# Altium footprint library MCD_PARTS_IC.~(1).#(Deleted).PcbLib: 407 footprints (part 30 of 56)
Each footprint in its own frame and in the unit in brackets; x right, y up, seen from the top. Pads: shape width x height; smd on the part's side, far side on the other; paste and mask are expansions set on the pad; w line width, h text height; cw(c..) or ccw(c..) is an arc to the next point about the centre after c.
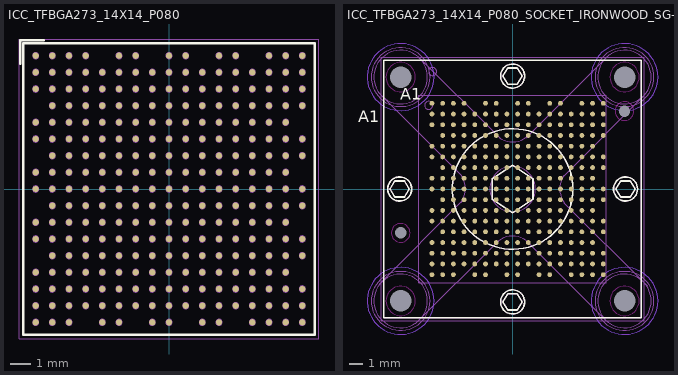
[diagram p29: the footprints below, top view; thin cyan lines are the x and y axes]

## ICC_TFBGA273_14X14_P080 [mm] "MCD-03616"
height 1.2
pads (273):
  round 0.3 smd mask+0.05: A1(-6.4,6.4) A2(-5.6,6.4) A3(-4.8,6.4) A4(-4,6.4) A6(-2.4,6.4) A7(-1.6,6.4) A9(0,6.4) A10(0.8,6.4) A12(2.4,6.4) A13(3.2,6.4) A15(4.8,6.4) A16(5.6,6.4) A17(6.4,6.4) B1(-6.4,5.6) B2(-5.6,5.6) B3(-4.8,5.6) B4(-4,5.6) B5(-3.2,5.6) B6(-2.4,5.6) B7(-1.6,5.6) B8(-0.8,5.6) B9(0,5.6) B10(0.8,5.6) B11(1.6,5.6) B12(2.4,5.6) B13(3.2,5.6) B14(4,5.6) B15(4.8,5.6) B16(5.6,5.6) B17(6.4,5.6) C1(-6.4,4.8) C2(-5.6,4.8) C3(-4.8,4.8) C4(-4,4.8) C5(-3.2,4.8) C6(-2.4,4.8) C7(-1.6,4.8) C8(-0.8,4.8) C9(0,4.8) C10(0.8,4.8) C11(1.6,4.8) C12(2.4,4.8) C13(3.2,4.8) C14(4,4.8) C15(4.8,4.8) C16(5.6,4.8) C17(6.4,4.8) D2(-5.6,4) D3(-4.8,4) D4(-4,4) D5(-3.2,4) D6(-2.4,4) D7(-1.6,4) D8(-0.8,4) D9(0,4) D10(0.8,4) D11(1.6,4) D12(2.4,4) D13(3.2,4) D14(4,4) D15(4.8,4) D16(5.6,4) D17(6.4,4) E1(-6.4,3.2) E2(-5.6,3.2) E3(-4.8,3.2) E4(-4,3.2) E5(-3.2,3.2) E6(-2.4,3.2) E7(-1.6,3.2) E8(-0.8,3.2) E9(0,3.2) E10(0.8,3.2) E11(1.6,3.2) E12(2.4,3.2) E13(3.2,3.2) E14(4,3.2) E15(4.8,3.2) E16(5.6,3.2) F1(-6.4,2.4) F2(-5.6,2.4) F3(-4.8,2.4) F4(-4,2.4) F5(-3.2,2.4) F6(-2.4,2.4) F7(-1.6,2.4) F8(-0.8,2.4) F9(0,2.4) F10(0.8,2.4) F11(1.6,2.4) F12(2.4,2.4) F13(3.2,2.4) F14(4,2.4) F15(4.8,2.4) F16(5.6,2.4) F17(6.4,2.4) G2(-5.6,1.6) G3(-4.8,1.6) G4(-4,1.6) G5(-3.2,1.6) G6(-2.4,1.6) G7(-1.6,1.6) G8(-0.8,1.6) G9(0,1.6) G10(0.8,1.6) G11(1.6,1.6) G12(2.4,1.6) G13(3.2,1.6) G14(4,1.6) G15(4.8,1.6) G16(5.6,1.6) G17(6.4,1.6) H1(-6.4,0.8) H2(-5.6,0.8) H3(-4.8,0.8) H4(-4,0.8) H5(-3.2,0.8) H6(-2.4,0.8) H7(-1.6,0.8) H8(-0.8,0.8) H9(0,0.8) H10(0.8,0.8) H11(1.6,0.8) H12(2.4,0.8) H13(3.2,0.8) H14(4,0.8) H15(4.8,0.8) H16(5.6,0.8) J1(-6.4,0) J2(-5.6,0) J3(-4.8,0) J4(-4,0) J5(-3.2,0) J6(-2.4,0) J7(-1.6,0) J8(-0.8,0) J9(0,0) J10(0.8,0) J11(1.6,0) J12(2.4,0) J13(3.2,0) J14(4,0) J15(4.8,0) J16(5.6,0) J17(6.4,0) K2(-5.6,-0.8) K3(-4.8,-0.8) K4(-4,-0.8) K5(-3.2,-0.8) K6(-2.4,-0.8) K7(-1.6,-0.8) K8(-0.8,-0.8) K9(0,-0.8) K10(0.8,-0.8) K11(1.6,-0.8) K12(2.4,-0.8) K13(3.2,-0.8) K14(4,-0.8) K15(4.8,-0.8) K16(5.6,-0.8) K17(6.4,-0.8) L1(-6.4,-1.6) L2(-5.6,-1.6) L3(-4.8,-1.6) L4(-4,-1.6) L5(-3.2,-1.6) L6(-2.4,-1.6) L7(-1.6,-1.6) L8(-0.8,-1.6) L9(0,-1.6) L10(0.8,-1.6) L11(1.6,-1.6) L12(2.4,-1.6) L13(3.2,-1.6) L14(4,-1.6) L15(4.8,-1.6) L16(5.6,-1.6) M1(-6.4,-2.4) M2(-5.6,-2.4) M3(-4.8,-2.4) M4(-4,-2.4) M5(-3.2,-2.4) M6(-2.4,-2.4) M7(-1.6,-2.4) M8(-0.8,-2.4) M9(0,-2.4) M10(0.8,-2.4) M11(1.6,-2.4) M12(2.4,-2.4) M13(3.2,-2.4) M14(4,-2.4) M15(4.8,-2.4) M16(5.6,-2.4) M17(6.4,-2.4) N2(-5.6,-3.2) N3(-4.8,-3.2) N4(-4,-3.2) N5(-3.2,-3.2) N6(-2.4,-3.2) N7(-1.6,-3.2) N8(-0.8,-3.2) N9(0,-3.2) N10(0.8,-3.2) N11(1.6,-3.2) N12(2.4,-3.2) N13(3.2,-3.2) N14(4,-3.2) N15(4.8,-3.2) N16(5.6,-3.2) N17(6.4,-3.2) P1(-6.4,-4) P2(-5.6,-4) P3(-4.8,-4) P4(-4,-4) P5(-3.2,-4) P6(-2.4,-4) P7(-1.6,-4) P8(-0.8,-4) P9(0,-4) P10(0.8,-4) P11(1.6,-4) P12(2.4,-4) P13(3.2,-4) P14(4,-4) P15(4.8,-4) P16(5.6,-4) R1(-6.4,-4.8) R2(-5.6,-4.8) R3(-4.8,-4.8) R4(-4,-4.8) R5(-3.2,-4.8) R6(-2.4,-4.8) R7(-1.6,-4.8) R8(-0.8,-4.8) R9(0,-4.8) R10(0.8,-4.8) R11(1.6,-4.8) R12(2.4,-4.8) R13(3.2,-4.8) R14(4,-4.8) R15(4.8,-4.8) R16(5.6,-4.8) R17(6.4,-4.8) T1(-6.4,-5.6) T2(-5.6,-5.6) T3(-4.8,-5.6) T4(-4,-5.6) T5(-3.2,-5.6) T6(-2.4,-5.6) T7(-1.6,-5.6) T8(-0.8,-5.6) T9(0,-5.6) T10(0.8,-5.6) T11(1.6,-5.6) T12(2.4,-5.6) T13(3.2,-5.6) T14(4,-5.6) T15(4.8,-5.6) T16(5.6,-5.6) T17(6.4,-5.6) U1(-6.4,-6.4) U2(-5.6,-6.4) U3(-4.8,-6.4) U5(-3.2,-6.4) U6(-2.4,-6.4) U8(-0.8,-6.4) U9(0,-6.4) U11(1.6,-6.4) U12(2.4,-6.4) U14(4,-6.4) U15(4.8,-6.4) U16(5.6,-6.4) U17(6.4,-6.4)
Top Overlay:
  lines w0.12: -7.15,6 -7.15,7.15 -6,7.15 ; -7,-7 -7,7 7,7 7,-7 -7,-7
M14-Top Assembly:
  drawing of 277 lines, arcs and shapes, not listed
  text "A1" at -6.865,6.079 h1
  text "'.Designator'" at 0,0 h0.75
M16-Top Courtyard:
  lines w0.01: -7.2,-7.2 7.2,-7.2 7.2,7.2 -7.2,7.2 -7.2,-7.2
3D body: height 1.2, standoff 0.29, extent -7,-7 7,7
3D body: height 1.21, standoff 1.2, extent -6.675,5.85 -5.875,6.65
3D body: height 0.37, standoff -0.03, extent -6.6,6.2 -6.2,6.6
3D body: height 0.37, standoff -0.03, extent -5.8,6.2 -5.4,6.6
3D body: height 0.37, standoff -0.03, extent -5,6.2 -4.6,6.6
3D body: height 0.37, standoff -0.03, extent -4.2,6.2 -3.8,6.6
3D body: height 0.37, standoff -0.03, extent -2.6,6.2 -2.2,6.6
3D body: height 0.37, standoff -0.03, extent -1.8,6.2 -1.4,6.6
3D body: height 0.37, standoff -0.03, extent -0.2,6.2 0.2,6.6
3D body: height 0.37, standoff -0.03, extent 0.6,6.2 1,6.6
3D body: height 0.37, standoff -0.03, extent 2.2,6.2 2.6,6.6
3D body: height 0.37, standoff -0.03, extent 3,6.2 3.4,6.6
3D body: height 0.37, standoff -0.03, extent 4.6,6.2 5,6.6
3D body: height 0.37, standoff -0.03, extent 5.4,6.2 5.8,6.6
3D body: height 0.37, standoff -0.03, extent 6.2,6.2 6.6,6.6
3D body: height 0.37, standoff -0.03, extent -6.6,5.4 -6.2,5.8
3D body: height 0.37, standoff -0.03, extent -5.8,5.4 -5.4,5.8
3D body: height 0.37, standoff -0.03, extent -5,5.4 -4.6,5.8
3D body: height 0.37, standoff -0.03, extent -4.2,5.4 -3.8,5.8
3D body: height 0.37, standoff -0.03, extent -3.4,5.4 -3,5.8
3D body: height 0.37, standoff -0.03, extent -2.6,5.4 -2.2,5.8
3D body: height 0.37, standoff -0.03, extent -1.8,5.4 -1.4,5.8
3D body: height 0.37, standoff -0.03, extent -1,5.4 -0.6,5.8
3D body: height 0.37, standoff -0.03, extent -0.2,5.4 0.2,5.8
3D body: height 0.37, standoff -0.03, extent 0.6,5.4 1,5.8
3D body: height 0.37, standoff -0.03, extent 1.4,5.4 1.8,5.8
3D body: height 0.37, standoff -0.03, extent 2.2,5.4 2.6,5.8
3D body: height 0.37, standoff -0.03, extent 3,5.4 3.4,5.8
3D body: height 0.37, standoff -0.03, extent 3.8,5.4 4.2,5.8
3D body: height 0.37, standoff -0.03, extent 4.6,5.4 5,5.8
3D body: height 0.37, standoff -0.03, extent 5.4,5.4 5.8,5.8
3D body: height 0.37, standoff -0.03, extent 6.2,5.4 6.6,5.8
3D body: height 0.37, standoff -0.03, extent -6.6,4.6 -6.2,5
3D body: height 0.37, standoff -0.03, extent -5.8,4.6 -5.4,5
3D body: height 0.37, standoff -0.03, extent -5,4.6 -4.6,5
3D body: height 0.37, standoff -0.03, extent -4.2,4.6 -3.8,5
3D body: height 0.37, standoff -0.03, extent -3.4,4.6 -3,5
3D body: height 0.37, standoff -0.03, extent -2.6,4.6 -2.2,5
3D body: height 0.37, standoff -0.03, extent -1.8,4.6 -1.4,5
3D body: height 0.37, standoff -0.03, extent -1,4.6 -0.6,5
3D body: height 0.37, standoff -0.03, extent -0.2,4.6 0.2,5
3D body: height 0.37, standoff -0.03, extent 0.6,4.6 1,5
3D body: height 0.37, standoff -0.03, extent 1.4,4.6 1.8,5
3D body: height 0.37, standoff -0.03, extent 2.2,4.6 2.6,5
3D body: height 0.37, standoff -0.03, extent 3,4.6 3.4,5
3D body: height 0.37, standoff -0.03, extent 3.8,4.6 4.2,5
3D body: height 0.37, standoff -0.03, extent 4.6,4.6 5,5
3D body: height 0.37, standoff -0.03, extent 5.4,4.6 5.8,5
3D body: height 0.37, standoff -0.03, extent 6.2,4.6 6.6,5
3D body: height 0.37, standoff -0.03, extent -5.8,3.8 -5.4,4.2
3D body: height 0.37, standoff -0.03, extent -5,3.8 -4.6,4.2
3D body: height 0.37, standoff -0.03, extent -4.2,3.8 -3.8,4.2
3D body: height 0.37, standoff -0.03, extent -3.4,3.8 -3,4.2
3D body: height 0.37, standoff -0.03, extent -2.6,3.8 -2.2,4.2
3D body: height 0.37, standoff -0.03, extent -1.8,3.8 -1.4,4.2
3D body: height 0.37, standoff -0.03, extent -1,3.8 -0.6,4.2
3D body: height 0.37, standoff -0.03, extent -0.2,3.8 0.2,4.2
3D body: height 0.37, standoff -0.03, extent 0.6,3.8 1,4.2
3D body: height 0.37, standoff -0.03, extent 1.4,3.8 1.8,4.2
3D body: height 0.37, standoff -0.03, extent 2.2,3.8 2.6,4.2
3D body: height 0.37, standoff -0.03, extent 3,3.8 3.4,4.2
3D body: height 0.37, standoff -0.03, extent 3.8,3.8 4.2,4.2
3D body: height 0.37, standoff -0.03, extent 4.6,3.8 5,4.2
3D body: height 0.37, standoff -0.03, extent 5.4,3.8 5.8,4.2
3D body: height 0.37, standoff -0.03, extent 6.2,3.8 6.6,4.2
3D body: height 0.37, standoff -0.03, extent -6.6,3 -6.2,3.4
3D body: height 0.37, standoff -0.03, extent -5.8,3 -5.4,3.4
3D body: height 0.37, standoff -0.03, extent -5,3 -4.6,3.4
3D body: height 0.37, standoff -0.03, extent -4.2,3 -3.8,3.4
3D body: height 0.37, standoff -0.03, extent -3.4,3 -3,3.4
3D body: height 0.37, standoff -0.03, extent -2.6,3 -2.2,3.4
3D body: height 0.37, standoff -0.03, extent -1.8,3 -1.4,3.4
3D body: height 0.37, standoff -0.03, extent -1,3 -0.6,3.4
3D body: height 0.37, standoff -0.03, extent -0.2,3 0.2,3.4
3D body: height 0.37, standoff -0.03, extent 0.6,3 1,3.4
3D body: height 0.37, standoff -0.03, extent 1.4,3 1.8,3.4
3D body: height 0.37, standoff -0.03, extent 2.2,3 2.6,3.4
3D body: height 0.37, standoff -0.03, extent 3,3 3.4,3.4
3D body: height 0.37, standoff -0.03, extent 3.8,3 4.2,3.4
3D body: height 0.37, standoff -0.03, extent 4.6,3 5,3.4
3D body: height 0.37, standoff -0.03, extent 5.4,3 5.8,3.4
3D body: height 0.37, standoff -0.03, extent -6.6,2.2 -6.2,2.6
3D body: height 0.37, standoff -0.03, extent -5.8,2.2 -5.4,2.6
3D body: height 0.37, standoff -0.03, extent -5,2.2 -4.6,2.6
3D body: height 0.37, standoff -0.03, extent -4.2,2.2 -3.8,2.6
3D body: height 0.37, standoff -0.03, extent -3.4,2.2 -3,2.6
3D body: height 0.37, standoff -0.03, extent -2.6,2.2 -2.2,2.6
3D body: height 0.37, standoff -0.03, extent -1.8,2.2 -1.4,2.6
3D body: height 0.37, standoff -0.03, extent -1,2.2 -0.6,2.6
3D body: height 0.37, standoff -0.03, extent -0.2,2.2 0.2,2.6
3D body: height 0.37, standoff -0.03, extent 0.6,2.2 1,2.6
3D body: height 0.37, standoff -0.03, extent 1.4,2.2 1.8,2.6
3D body: height 0.37, standoff -0.03, extent 2.2,2.2 2.6,2.6
3D body: height 0.37, standoff -0.03, extent 3,2.2 3.4,2.6
3D body: height 0.37, standoff -0.03, extent 3.8,2.2 4.2,2.6
3D body: height 0.37, standoff -0.03, extent 4.6,2.2 5,2.6
3D body: height 0.37, standoff -0.03, extent 5.4,2.2 5.8,2.6
3D body: height 0.37, standoff -0.03, extent 6.2,2.2 6.6,2.6
3D body: height 0.37, standoff -0.03, extent -5.8,1.4 -5.4,1.8
3D body: height 0.37, standoff -0.03, extent -5,1.4 -4.6,1.8
3D body: height 0.37, standoff -0.03, extent -4.2,1.4 -3.8,1.8
3D body: height 0.37, standoff -0.03, extent -3.4,1.4 -3,1.8
3D body: height 0.37, standoff -0.03, extent -2.6,1.4 -2.2,1.8
3D body: height 0.37, standoff -0.03, extent -1.8,1.4 -1.4,1.8
3D body: height 0.37, standoff -0.03, extent -1,1.4 -0.6,1.8
3D body: height 0.37, standoff -0.03, extent -0.2,1.4 0.2,1.8
3D body: height 0.37, standoff -0.03, extent 0.6,1.4 1,1.8
3D body: height 0.37, standoff -0.03, extent 1.4,1.4 1.8,1.8
3D body: height 0.37, standoff -0.03, extent 2.2,1.4 2.6,1.8
3D body: height 0.37, standoff -0.03, extent 3,1.4 3.4,1.8
3D body: height 0.37, standoff -0.03, extent 3.8,1.4 4.2,1.8
3D body: height 0.37, standoff -0.03, extent 4.6,1.4 5,1.8
3D body: height 0.37, standoff -0.03, extent 5.4,1.4 5.8,1.8
3D body: height 0.37, standoff -0.03, extent 6.2,1.4 6.6,1.8
3D body: height 0.37, standoff -0.03, extent -6.6,0.6 -6.2,1
3D body: height 0.37, standoff -0.03, extent -5.8,0.6 -5.4,1
3D body: height 0.37, standoff -0.03, extent -5,0.6 -4.6,1
3D body: height 0.37, standoff -0.03, extent -4.2,0.6 -3.8,1
3D body: height 0.37, standoff -0.03, extent -3.4,0.6 -3,1
3D body: height 0.37, standoff -0.03, extent -2.6,0.6 -2.2,1
3D body: height 0.37, standoff -0.03, extent -1.8,0.6 -1.4,1
3D body: height 0.37, standoff -0.03, extent -1,0.6 -0.6,1
3D body: height 0.37, standoff -0.03, extent -0.2,0.6 0.2,1
3D body: height 0.37, standoff -0.03, extent 0.6,0.6 1,1
3D body: height 0.37, standoff -0.03, extent 1.4,0.6 1.8,1
3D body: height 0.37, standoff -0.03, extent 2.2,0.6 2.6,1
3D body: height 0.37, standoff -0.03, extent 3,0.6 3.4,1
3D body: height 0.37, standoff -0.03, extent 3.8,0.6 4.2,1
3D body: height 0.37, standoff -0.03, extent 4.6,0.6 5,1
3D body: height 0.37, standoff -0.03, extent 5.4,0.6 5.8,1
3D body: height 0.37, standoff -0.03, extent -6.6,-0.2 -6.2,0.2
3D body: height 0.37, standoff -0.03, extent -5.8,-0.2 -5.4,0.2
3D body: height 0.37, standoff -0.03, extent -5,-0.2 -4.6,0.2
3D body: height 0.37, standoff -0.03, extent -4.2,-0.2 -3.8,0.2
3D body: height 0.37, standoff -0.03, extent -3.4,-0.2 -3,0.2
3D body: height 0.37, standoff -0.03, extent -2.6,-0.2 -2.2,0.2
3D body: height 0.37, standoff -0.03, extent -1.8,-0.2 -1.4,0.2
3D body: height 0.37, standoff -0.03, extent -1,-0.2 -0.6,0.2
3D body: height 0.37, standoff -0.03, extent -0.2,-0.2 0.2,0.2
3D body: height 0.37, standoff -0.03, extent 0.6,-0.2 1,0.2
3D body: height 0.37, standoff -0.03, extent 1.4,-0.2 1.8,0.2
3D body: height 0.37, standoff -0.03, extent 2.2,-0.2 2.6,0.2
3D body: height 0.37, standoff -0.03, extent 3,-0.2 3.4,0.2
3D body: height 0.37, standoff -0.03, extent 3.8,-0.2 4.2,0.2
3D body: height 0.37, standoff -0.03, extent 4.6,-0.2 5,0.2
3D body: height 0.37, standoff -0.03, extent 5.4,-0.2 5.8,0.2
3D body: height 0.37, standoff -0.03, extent 6.2,-0.2 6.6,0.2
3D body: height 0.37, standoff -0.03, extent -5.8,-1 -5.4,-0.6
3D body: height 0.37, standoff -0.03, extent -5,-1 -4.6,-0.6
3D body: height 0.37, standoff -0.03, extent -4.2,-1 -3.8,-0.6
3D body: height 0.37, standoff -0.03, extent -3.4,-1 -3,-0.6
3D body: height 0.37, standoff -0.03, extent -2.6,-1 -2.2,-0.6
3D body: height 0.37, standoff -0.03, extent -1.8,-1 -1.4,-0.6
3D body: height 0.37, standoff -0.03, extent -1,-1 -0.6,-0.6
3D body: height 0.37, standoff -0.03, extent -0.2,-1 0.2,-0.6
3D body: height 0.37, standoff -0.03, extent 0.6,-1 1,-0.6
3D body: height 0.37, standoff -0.03, extent 1.4,-1 1.8,-0.6
3D body: height 0.37, standoff -0.03, extent 2.2,-1 2.6,-0.6
3D body: height 0.37, standoff -0.03, extent 3,-1 3.4,-0.6
3D body: height 0.37, standoff -0.03, extent 3.8,-1 4.2,-0.6
3D body: height 0.37, standoff -0.03, extent 4.6,-1 5,-0.6
3D body: height 0.37, standoff -0.03, extent 5.4,-1 5.8,-0.6
3D body: height 0.37, standoff -0.03, extent 6.2,-1 6.6,-0.6
3D body: height 0.37, standoff -0.03, extent -6.6,-1.8 -6.2,-1.4
3D body: height 0.37, standoff -0.03, extent -5.8,-1.8 -5.4,-1.4
3D body: height 0.37, standoff -0.03, extent -5,-1.8 -4.6,-1.4
3D body: height 0.37, standoff -0.03, extent -4.2,-1.8 -3.8,-1.4
3D body: height 0.37, standoff -0.03, extent -3.4,-1.8 -3,-1.4
3D body: height 0.37, standoff -0.03, extent -2.6,-1.8 -2.2,-1.4
3D body: height 0.37, standoff -0.03, extent -1.8,-1.8 -1.4,-1.4
3D body: height 0.37, standoff -0.03, extent -1,-1.8 -0.6,-1.4
3D body: height 0.37, standoff -0.03, extent -0.2,-1.8 0.2,-1.4
3D body: height 0.37, standoff -0.03, extent 0.6,-1.8 1,-1.4
3D body: height 0.37, standoff -0.03, extent 1.4,-1.8 1.8,-1.4
3D body: height 0.37, standoff -0.03, extent 2.2,-1.8 2.6,-1.4
3D body: height 0.37, standoff -0.03, extent 3,-1.8 3.4,-1.4
3D body: height 0.37, standoff -0.03, extent 3.8,-1.8 4.2,-1.4
3D body: height 0.37, standoff -0.03, extent 4.6,-1.8 5,-1.4
3D body: height 0.37, standoff -0.03, extent 5.4,-1.8 5.8,-1.4
3D body: height 0.37, standoff -0.03, extent -6.6,-2.6 -6.2,-2.2
3D body: height 0.37, standoff -0.03, extent -5.8,-2.6 -5.4,-2.2
3D body: height 0.37, standoff -0.03, extent -5,-2.6 -4.6,-2.2
3D body: height 0.37, standoff -0.03, extent -4.2,-2.6 -3.8,-2.2
3D body: height 0.37, standoff -0.03, extent -3.4,-2.6 -3,-2.2
3D body: height 0.37, standoff -0.03, extent -2.6,-2.6 -2.2,-2.2
3D body: height 0.37, standoff -0.03, extent -1.8,-2.6 -1.4,-2.2
3D body: height 0.37, standoff -0.03, extent -1,-2.6 -0.6,-2.2
3D body: height 0.37, standoff -0.03, extent -0.2,-2.6 0.2,-2.2
3D body: height 0.37, standoff -0.03, extent 0.6,-2.6 1,-2.2
3D body: height 0.37, standoff -0.03, extent 1.4,-2.6 1.8,-2.2
3D body: height 0.37, standoff -0.03, extent 2.2,-2.6 2.6,-2.2
3D body: height 0.37, standoff -0.03, extent 3,-2.6 3.4,-2.2
3D body: height 0.37, standoff -0.03, extent 3.8,-2.6 4.2,-2.2
3D body: height 0.37, standoff -0.03, extent 4.6,-2.6 5,-2.2
3D body: height 0.37, standoff -0.03, extent 5.4,-2.6 5.8,-2.2
3D body: height 0.37, standoff -0.03, extent 6.2,-2.6 6.6,-2.2
3D body: height 0.37, standoff -0.03, extent -5.8,-3.4 -5.4,-3
3D body: height 0.37, standoff -0.03, extent -5,-3.4 -4.6,-3
3D body: height 0.37, standoff -0.03, extent -4.2,-3.4 -3.8,-3
3D body: height 0.37, standoff -0.03, extent -3.4,-3.4 -3,-3
3D body: height 0.37, standoff -0.03, extent -2.6,-3.4 -2.2,-3
3D body: height 0.37, standoff -0.03, extent -1.8,-3.4 -1.4,-3
3D body: height 0.37, standoff -0.03, extent -1,-3.4 -0.6,-3
3D body: height 0.37, standoff -0.03, extent -0.2,-3.4 0.2,-3
3D body: height 0.37, standoff -0.03, extent 0.6,-3.4 1,-3
3D body: height 0.37, standoff -0.03, extent 1.4,-3.4 1.8,-3
3D body: height 0.37, standoff -0.03, extent 2.2,-3.4 2.6,-3
3D body: height 0.37, standoff -0.03, extent 3,-3.4 3.4,-3
3D body: height 0.37, standoff -0.03, extent 3.8,-3.4 4.2,-3
3D body: height 0.37, standoff -0.03, extent 4.6,-3.4 5,-3
3D body: height 0.37, standoff -0.03, extent 5.4,-3.4 5.8,-3
3D body: height 0.37, standoff -0.03, extent 6.2,-3.4 6.6,-3
3D body: height 0.37, standoff -0.03, extent -6.6,-4.2 -6.2,-3.8
3D body: height 0.37, standoff -0.03, extent -5.8,-4.2 -5.4,-3.8
3D body: height 0.37, standoff -0.03, extent -5,-4.2 -4.6,-3.8
3D body: height 0.37, standoff -0.03, extent -4.2,-4.2 -3.8,-3.8
3D body: height 0.37, standoff -0.03, extent -3.4,-4.2 -3,-3.8
3D body: height 0.37, standoff -0.03, extent -2.6,-4.2 -2.2,-3.8
3D body: height 0.37, standoff -0.03, extent -1.8,-4.2 -1.4,-3.8
3D body: height 0.37, standoff -0.03, extent -1,-4.2 -0.6,-3.8
3D body: height 0.37, standoff -0.03, extent -0.2,-4.2 0.2,-3.8
3D body: height 0.37, standoff -0.03, extent 0.6,-4.2 1,-3.8
3D body: height 0.37, standoff -0.03, extent 1.4,-4.2 1.8,-3.8
3D body: height 0.37, standoff -0.03, extent 2.2,-4.2 2.6,-3.8
3D body: height 0.37, standoff -0.03, extent 3,-4.2 3.4,-3.8
3D body: height 0.37, standoff -0.03, extent 3.8,-4.2 4.2,-3.8
3D body: height 0.37, standoff -0.03, extent 4.6,-4.2 5,-3.8
3D body: height 0.37, standoff -0.03, extent 5.4,-4.2 5.8,-3.8
3D body: height 0.37, standoff -0.03, extent -6.6,-5 -6.2,-4.6
3D body: height 0.37, standoff -0.03, extent -5.8,-5 -5.4,-4.6
3D body: height 0.37, standoff -0.03, extent -5,-5 -4.6,-4.6
3D body: height 0.37, standoff -0.03, extent -4.2,-5 -3.8,-4.6
3D body: height 0.37, standoff -0.03, extent -3.4,-5 -3,-4.6
3D body: height 0.37, standoff -0.03, extent -2.6,-5 -2.2,-4.6
3D body: height 0.37, standoff -0.03, extent -1.8,-5 -1.4,-4.6
3D body: height 0.37, standoff -0.03, extent -1,-5 -0.6,-4.6
3D body: height 0.37, standoff -0.03, extent -0.2,-5 0.2,-4.6
3D body: height 0.37, standoff -0.03, extent 0.6,-5 1,-4.6
3D body: height 0.37, standoff -0.03, extent 1.4,-5 1.8,-4.6
3D body: height 0.37, standoff -0.03, extent 2.2,-5 2.6,-4.6
3D body: height 0.37, standoff -0.03, extent 3,-5 3.4,-4.6
3D body: height 0.37, standoff -0.03, extent 3.8,-5 4.2,-4.6
3D body: height 0.37, standoff -0.03, extent 4.6,-5 5,-4.6
3D body: height 0.37, standoff -0.03, extent 5.4,-5 5.8,-4.6
3D body: height 0.37, standoff -0.03, extent 6.2,-5 6.6,-4.6
3D body: height 0.37, standoff -0.03, extent -6.6,-5.8 -6.2,-5.4
3D body: height 0.37, standoff -0.03, extent -5.8,-5.8 -5.4,-5.4
3D body: height 0.37, standoff -0.03, extent -5,-5.8 -4.6,-5.4
3D body: height 0.37, standoff -0.03, extent -4.2,-5.8 -3.8,-5.4
3D body: height 0.37, standoff -0.03, extent -3.4,-5.8 -3,-5.4
3D body: height 0.37, standoff -0.03, extent -2.6,-5.8 -2.2,-5.4
3D body: height 0.37, standoff -0.03, extent -1.8,-5.8 -1.4,-5.4
3D body: height 0.37, standoff -0.03, extent -1,-5.8 -0.6,-5.4
3D body: height 0.37, standoff -0.03, extent -0.2,-5.8 0.2,-5.4
3D body: height 0.37, standoff -0.03, extent 0.6,-5.8 1,-5.4
3D body: height 0.37, standoff -0.03, extent 1.4,-5.8 1.8,-5.4
3D body: height 0.37, standoff -0.03, extent 2.2,-5.8 2.6,-5.4
3D body: height 0.37, standoff -0.03, extent 3,-5.8 3.4,-5.4
3D body: height 0.37, standoff -0.03, extent 3.8,-5.8 4.2,-5.4
3D body: height 0.37, standoff -0.03, extent 4.6,-5.8 5,-5.4
3D body: height 0.37, standoff -0.03, extent 5.4,-5.8 5.8,-5.4
3D body: height 0.37, standoff -0.03, extent 6.2,-5.8 6.6,-5.4
3D body: height 0.37, standoff -0.03, extent -6.6,-6.6 -6.2,-6.2
3D body: height 0.37, standoff -0.03, extent -5.8,-6.6 -5.4,-6.2
3D body: height 0.37, standoff -0.03, extent -5,-6.6 -4.6,-6.2
3D body: height 0.37, standoff -0.03, extent -3.4,-6.6 -3,-6.2
3D body: height 0.37, standoff -0.03, extent -2.6,-6.6 -2.2,-6.2
3D body: height 0.37, standoff -0.03, extent -0.2,-6.6 0.2,-6.2
3D body: height 0.37, standoff -0.03, extent 1.4,-6.6 1.8,-6.2
3D body: height 0.37, standoff -0.03, extent 2.2,-6.6 2.6,-6.2
3D body: height 0.37, standoff -0.03, extent 3.8,-6.6 4.2,-6.2
3D body: height 0.37, standoff -0.03, extent 4.6,-6.6 5,-6.2
3D body: height 0.37, standoff -0.03, extent 5.4,-6.6 5.8,-6.2
3D body: height 0.37, standoff -0.03, extent 6.2,-6.6 6.6,-6.2
3D body: height 0.37, standoff -0.03, extent -1,-6.6 -0.6,-6.2

## ICC_TFBGA273_14X14_P080_SOCKET_IRONWOOD_SG-BGA-6112MF [mm] "MCD-03616"
height 8.25
pads (279):
  round 0.36 smd mask+0.05: A1(-6.025,6.4) A2(-5.225,6.4) A3(-4.425,6.4) A4(-3.625,6.4) A6(-2.025,6.4) A7(-1.225,6.4) A9(0.375,6.4) A10(1.175,6.4) A12(2.775,6.4) A13(3.575,6.4) A15(5.175,6.4) A16(5.975,6.4) A17(6.775,6.4) B1(-6.025,5.6) B2(-5.225,5.6) B3(-4.425,5.6) B4(-3.625,5.6) B5(-2.825,5.6) B6(-2.025,5.6) B7(-1.225,5.6) B8(-0.425,5.6) B9(0.375,5.6) B10(1.175,5.6) B11(1.975,5.6) B12(2.775,5.6) B13(3.575,5.6) B14(4.375,5.6) B15(5.175,5.6) B16(5.975,5.6) B17(6.775,5.6) C1(-6.025,4.8) C2(-5.225,4.8) C3(-4.425,4.8) C4(-3.625,4.8) C5(-2.825,4.8) C6(-2.025,4.8) C7(-1.225,4.8) C8(-0.425,4.8) C9(0.375,4.8) C10(1.175,4.8) C11(1.975,4.8) C12(2.775,4.8) C13(3.575,4.8) C14(4.375,4.8) C15(5.175,4.8) C16(5.975,4.8) C17(6.775,4.8) D2(-5.225,4) D3(-4.425,4) D4(-3.625,4) D5(-2.825,4) D6(-2.025,4) D7(-1.225,4) D8(-0.425,4) D9(0.375,4) D10(1.175,4) D11(1.975,4) D12(2.775,4) D13(3.575,4) D14(4.375,4) D15(5.175,4) D16(5.975,4) D17(6.775,4) E1(-6.025,3.2) E2(-5.225,3.2) E3(-4.425,3.2) E4(-3.625,3.2) E5(-2.825,3.2) E6(-2.025,3.2) E7(-1.225,3.2) E8(-0.425,3.2) E9(0.375,3.2) E10(1.175,3.2) E11(1.975,3.2) E12(2.775,3.2) E13(3.575,3.2) E14(4.375,3.2) E15(5.175,3.2) E16(5.975,3.2) F1(-6.025,2.4) F2(-5.225,2.4) F3(-4.425,2.4) F4(-3.625,2.4) F5(-2.825,2.4) F6(-2.025,2.4) F7(-1.225,2.4) F8(-0.425,2.4) F9(0.375,2.4) F10(1.175,2.4) F11(1.975,2.4) F12(2.775,2.4) F13(3.575,2.4) F14(4.375,2.4) F15(5.175,2.4) F16(5.975,2.4) F17(6.775,2.4) G2(-5.225,1.6) G3(-4.425,1.6) G4(-3.625,1.6) G5(-2.825,1.6) G6(-2.025,1.6) G7(-1.225,1.6) G8(-0.425,1.6) G9(0.375,1.6) G10(1.175,1.6) G11(1.975,1.6) G12(2.775,1.6) G13(3.575,1.6) G14(4.375,1.6) G15(5.175,1.6) G16(5.975,1.6) G17(6.775,1.6) H1(-6.025,0.8) H2(-5.225,0.8) H3(-4.425,0.8) H4(-3.625,0.8) H5(-2.825,0.8) H6(-2.025,0.8) H7(-1.225,0.8) H8(-0.425,0.8) H9(0.375,0.8) H10(1.175,0.8) H11(1.975,0.8) H12(2.775,0.8) H13(3.575,0.8) H14(4.375,0.8) H15(5.175,0.8) H16(5.975,0.8) J1(-6.025,0) J2(-5.225,0) J3(-4.425,0) J4(-3.625,0) J5(-2.825,0) J6(-2.025,0) J7(-1.225,0) J8(-0.425,0) J9(0.375,0) J10(1.175,0) J11(1.975,0) J12(2.775,0) J13(3.575,0) J14(4.375,0) J15(5.175,0) J16(5.975,0) J17(6.775,0) K2(-5.225,-0.8) K3(-4.425,-0.8) K4(-3.625,-0.8) K5(-2.825,-0.8) K6(-2.025,-0.8) K7(-1.225,-0.8) K8(-0.425,-0.8) K9(0.375,-0.8) K10(1.175,-0.8) K11(1.975,-0.8) K12(2.775,-0.8) K13(3.575,-0.8) K14(4.375,-0.8) K15(5.175,-0.8) K16(5.975,-0.8) K17(6.775,-0.8) L1(-6.025,-1.6) L2(-5.225,-1.6) L3(-4.425,-1.6) L4(-3.625,-1.6) L5(-2.825,-1.6) L6(-2.025,-1.6) L7(-1.225,-1.6) L8(-0.425,-1.6) L9(0.375,-1.6) L10(1.175,-1.6) L11(1.975,-1.6) L12(2.775,-1.6) L13(3.575,-1.6) L14(4.375,-1.6) L15(5.175,-1.6) L16(5.975,-1.6) M1(-6.025,-2.4) M2(-5.225,-2.4) M3(-4.425,-2.4) M4(-3.625,-2.4) M5(-2.825,-2.4) M6(-2.025,-2.4) M7(-1.225,-2.4) M8(-0.425,-2.4) M9(0.375,-2.4) M10(1.175,-2.4) M11(1.975,-2.4) M12(2.775,-2.4) M13(3.575,-2.4) M14(4.375,-2.4) M15(5.175,-2.4) M16(5.975,-2.4) M17(6.775,-2.4) N2(-5.225,-3.2) N3(-4.425,-3.2) N4(-3.625,-3.2) N5(-2.825,-3.2) N6(-2.025,-3.2) N7(-1.225,-3.2) N8(-0.425,-3.2) N9(0.375,-3.2) N10(1.175,-3.2) N11(1.975,-3.2) N12(2.775,-3.2) N13(3.575,-3.2) N14(4.375,-3.2) N15(5.175,-3.2) N16(5.975,-3.2) N17(6.775,-3.2) P1(-6.025,-4) P2(-5.225,-4) P3(-4.425,-4) P4(-3.625,-4) P5(-2.825,-4) P6(-2.025,-4) P7(-1.225,-4) P8(-0.425,-4) P9(0.375,-4) P10(1.175,-4) P11(1.975,-4) P12(2.775,-4) P13(3.575,-4) P14(4.375,-4) P15(5.175,-4) P16(5.975,-4) R1(-6.025,-4.8) R2(-5.225,-4.8) R3(-4.425,-4.8) R4(-3.625,-4.8) R5(-2.825,-4.8) R6(-2.025,-4.8) R7(-1.225,-4.8) R8(-0.425,-4.8) R9(0.375,-4.8) R10(1.175,-4.8) R11(1.975,-4.8) R12(2.775,-4.8) R13(3.575,-4.8) R14(4.375,-4.8) R15(5.175,-4.8) R16(5.975,-4.8) R17(6.775,-4.8) T1(-6.025,-5.6) T2(-5.225,-5.6) T3(-4.425,-5.6) T4(-3.625,-5.6) T5(-2.825,-5.6) T6(-2.025,-5.6) T7(-1.225,-5.6) T8(-0.425,-5.6) T9(0.375,-5.6) T10(1.175,-5.6) T11(1.975,-5.6) T12(2.775,-5.6) T13(3.575,-5.6) T14(4.375,-5.6) T15(5.175,-5.6) T16(5.975,-5.6) T17(6.775,-5.6) U1(-6.025,-6.4) U2(-5.225,-6.4) U3(-4.425,-6.4) U5(-2.825,-6.4) U6(-2.025,-6.4) U8(-0.425,-6.4) U9(0.375,-6.4) U11(1.975,-6.4) U12(2.775,-6.4) U14(4.375,-6.4) U15(5.175,-6.4) U16(5.975,-6.4) U17(6.775,-6.4)
  round 0 hole 1.61 unplated mask+0.05: NPTH1(-8.363,8.363) NPTH2(8.363,8.363) NPTH3(8.363,-8.363) NPTH4(-8.363,-8.363)
  round 0 hole 0.85 unplated mask+0.05: NPTH5(-8.363,-3.283) NPTH6(8.363,5.823)
Bottom Layer keep-out:
  circle w0.01: c-8.362,8.362 r2.5
  circle w0.01: c8.363,8.363 r2.5
  circle w0.01: c8.363,-8.363 r2.5
  circle w0.01: c-8.363,-8.363 r2.5
Top Overlay:
  circle w0.12: c0,0 r4.5
  circle w0.12: c-8.438,0 r0.9
  circle w0.12: c0,-8.438 r0.9
  circle w0.12: c8.438,0 r0.9
  circle w0.12: c0,8.437 r0.9
  lines w0.12: -9.613,-9.613 9.613,-9.613 9.613,9.613 -9.613,9.613 -9.613,-9.613 ; -9.158,0 -8.798,0.6 -8.078,0.6 -7.718,0 -8.078,-0.6 -8.798,-0.6 -9.158,0 ; -1.524,-0.762 0,-1.778 1.524,-0.762 1.524,0.762 0,1.778 -1.524,0.762 -1.524,-0.762 ; -0.72,-8.438 -0.36,-7.838 0.36,-7.838 0.72,-8.438 0.36,-9.038 -0.36,-9.038 -0.72,-8.438 ; -0.72,8.437 -0.36,7.837 0.36,7.837 0.72,8.437 0.36,9.037 -0.36,9.037 -0.72,8.437 ; 7.718,0 8.078,0.6 8.798,0.6 9.158,0 8.798,-0.6 8.078,-0.6 7.718,0
  text "A1" at -8.4,6.375 h1.5
  text "A1" at -11.55,4.675 h1.5
Bottom Overlay:
  circle w0.12: c-8.363,8.363 r2.5
  circle w0.12: c-8.362,-8.362 r2.5
  circle w0.12: c8.362,-8.362 r2.5
  circle w0.12: c8.363,8.363 r2.5
Keep-Out Layer:
  circle w0.01: c8.363,5.823 r0.7
  circle w0.01: c-8.363,-3.283 r0.7
  circle w0.01: c-8.362,8.362 r1.1
  circle w0.01: c8.363,8.363 r1.1
  circle w0.01: c8.362,-8.362 r1.1
  circle w0.01: c-8.363,-8.363 r1.1
M14-Top Assembly:
  circle w0.01: c0,0 r4.5
  circle w0.01: c-8.438,0 r0.9
  circle w0.01: c0,-8.438 r0.9
  circle w0.01: c8.438,0 r0.9
  circle w0.01: c0,8.437 r0.9
  circle w0.01: c-5.975,8.775 r0.3
  circle w0.01: c-6.275,6.25 r0.3
  lines w0.01: -9.613,-9.613 9.613,-9.613 9.613,3.562 9.613,9.613 -9.613,9.613 -9.613,-9.613 ; -9.158,0 -8.798,-0.6 -8.078,-0.6 -7.718,0 -8.078,0.6 -8.798,0.6 -9.158,0 ; -7,-7 7,-7 7,7 -7,7 -7,-7 ; -1.524,-0.762 0,-1.778 1.524,-0.762 1.524,0.762 0,1.778 -1.524,0.762 -1.524,-0.762 ; -0.72,-8.438 -0.36,-9.038 0.36,-9.038 0.72,-8.438 0.36,-7.838 -0.36,-7.838 -0.72,-8.438 ; -0.72,8.437 -0.36,9.037 0.36,9.037 0.72,8.437 0.36,7.837 -0.36,7.837 -0.72,8.437 ; 7.718,0 8.078,-0.6 8.798,-0.6 9.158,0 8.798,0.6 8.078,0.6 7.718,0
  text "'.Designator'" at 0,0 h0.75
M15-Bottom Assembly:
  circle w0.01: c-8.362,8.362 r2
  circle w0.01: c-8.362,-8.362 r2
  circle w0.01: c8.363,-8.363 r2
  circle w0.01: c8.362,8.362 r2
  lines w0.01: -10.044,7.235 -3.82,1.011 ; -9.929,-7.075 -3.82,-0.967 ; -7.235,-10.044 -1.011,-3.82 ; -7.075,9.929 -0.967,3.82 ; -3.848,1.029 cw(c-5.325,0) -3.826,-0.996 ; -1.029,-3.848 cw(c0,-5.325) 0.996,-3.826 ; -0.996,3.826 ccw(c0,5.325) 1.029,3.848 ; 0.967,-3.82 7.075,-9.929 ; 1.011,3.82 7.235,10.044 ; 3.82,-1.011 10.044,-7.235 ; 3.82,0.967 9.928,7.075 ; 3.826,0.996 ccw(c5.325,0) 3.848,-1.029
M16-Top Courtyard:
  lines w0.01: -9.825,-9.825 -9.825,9.825 9.825,9.825 9.825,-9.825 -9.825,-9.825
M17-Bottom Courtyard:
  circle w0.01: c0,0 r1.7
  circle w0.01: c-8.362,8.362 r2.2
  circle w0.01: c8.362,8.362 r2.2
  circle w0.01: c8.362,-8.362 r2.2
  circle w0.01: c-8.362,-8.362 r2.2
3D body: height 6, standoff 5, extent -9.33,-0.898 -7.537,0.898
3D body: height 6.01, standoff 6, extent -9.158,-0.6 -7.718,0.6
3D body: height 6, standoff 5, extent -0.893,7.539 0.9,9.336
3D body: height 6.01, standoff 6, extent -0.72,7.837 0.72,9.037
3D body: height 6, standoff 5, extent 7.545,-0.898 9.338,0.898
3D body: height 6.01, standoff 6, extent 7.717,-0.6 9.158,0.6
3D body: height 6, standoff 5, extent -0.893,-9.336 0.9,-7.539
3D body: height 6.01, standoff 6, extent -0.72,-9.038 0.72,-7.838
3D body: height 9.85, standoff 1.6, extent -2.5,-2.497 2.5,2.497
3D body: height 9.86, standoff 9.85, extent -1.025,-1.212 1.025,1.213
3D body: height 5, standoff 0, extent -9.613,-9.613 9.613,9.613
